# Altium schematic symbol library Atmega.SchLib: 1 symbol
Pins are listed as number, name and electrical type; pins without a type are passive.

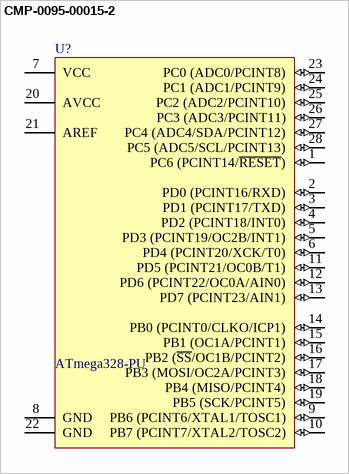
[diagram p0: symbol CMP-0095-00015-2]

## CMP-0095-00015-2
designator U?, comment ATmega328-PU
8-bit AVR Microcontroller, 32KB Flash, 1KB EEPROM, 2KB SRAM, 28-pin PDIP, Industrial Grade (-40°C to 85°C)
footprint 28P3 (28-Pin Plastic Dual In-Line Package (PDIP))
pins: 1 PC6 (PCINT14/~{RESET}) (io), 2 PD0 (PCINT16/RXD) (io), 3 PD1 (PCINT17/TXD) (io), 4 PD2 (PCINT18/INT0) (io), 5 PD3 (PCINT19/OC2B/INT1) (io), 6 PD4 (PCINT20/XCK/T0) (io), 7 VCC (power), 8 GND (power), 9 PB6 (PCINT6/XTAL1/TOSC1) (io), 10 PB7 (PCINT7/XTAL2/TOSC2) (io), 11 PD5 (PCINT21/OC0B/T1) (io), 12 PD6 (PCINT22/OC0A/AIN0) (io), 13 PD7 (PCINT23/AIN1) (io), 14 PB0 (PCINT0/CLKO/ICP1) (io), 15 PB1 (OC1A/PCINT1) (io), 16 PB2 (~{SS}/OC1B/PCINT2) (io), 17 PB3 (MOSI/OC2A/PCINT3) (io), 18 PB4 (MISO/PCINT4) (io), 19 PB5 (SCK/PCINT5) (io), 20 AVCC (power), 21 AREF (power), 22 GND (power), 23 PC0 (ADC0/PCINT8) (io), 24 PC1 (ADC1/PCINT9) (io), 25 PC2 (ADC2/PCINT10) (io), 26 PC3 (ADC3/PCINT11) (io), 27 PC4 (ADC4/SDA/PCINT12) (io), 28 PC5 (ADC5/SCL/PCINT13) (io)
